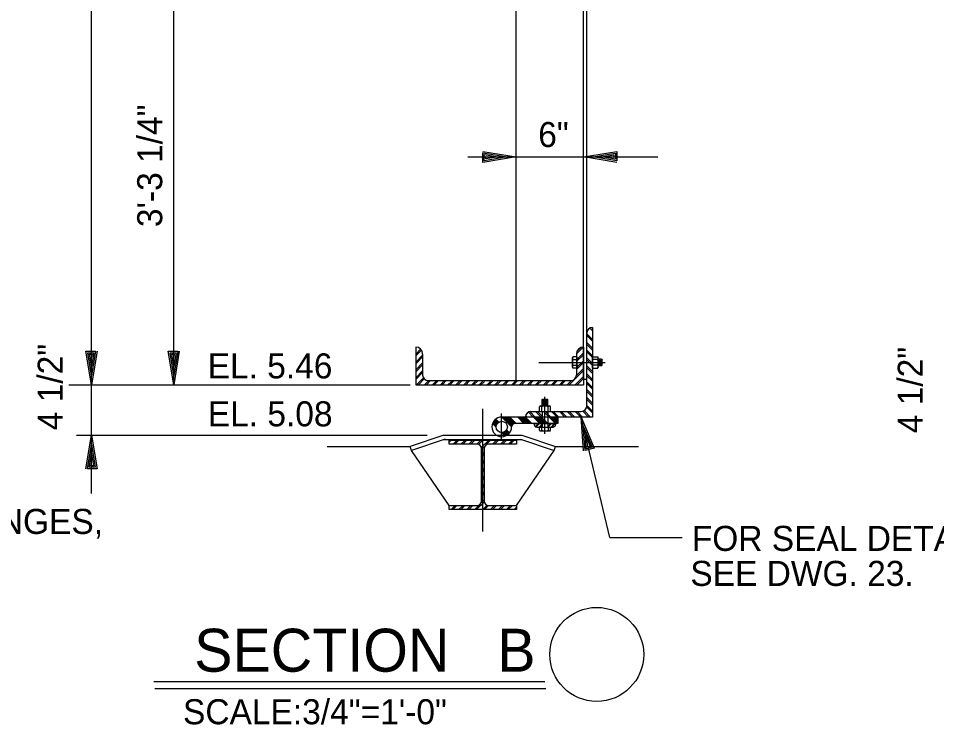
# Model space of a CAD drawing. Extents: x 0.6 to 54, y 0.6 to 38.
# Drawn here: x 40.38 to 47.23, y 11.68 to 16.93 of the extents above; entities that cross this region are included whole.
import ezdxf

# ---------------------------------------------------------------- set-up
doc = ezdxf.new("R2010")
doc.units = 0
for name, color, linetype in [('Level 1', 7, 'Continuous'), ('Level 10', 7, 'Continuous'), ('Level 13', 7, 'Continuous'), ('Level 2', 7, 'Continuous'), ('Level 25', 7, 'Continuous'), ('Level 3', 7, 'Continuous'), ('Level 36', 7, 'Continuous'), ('Level 50', 7, 'Continuous')]:
    doc.layers.add(name, color=color, linetype=linetype)

msp = doc.modelspace()

# ---------------------------------------------------------------- linework, layer by layer
at = {"layer": 'Level 1'}
msp.add_line((44.2486, 13.8913), (44.3689, 13.8913), dxfattribs=at)
for centre, start, end in [((44.251, 13.9174), 180, 270), ((44.3656, 13.9174), 270, 0)]:
    msp.add_arc(centre, 0.026, start, end, dxfattribs=at)
at = {"layer": 'Level 10'}
for p, q in [((44.2316, 13.9174), (44.2257, 13.9115)), ((44.2375, 13.9174), (44.2271, 13.907)), ((44.261, 13.9174), (44.2383, 13.8947)), ((44.2669, 13.9174), (44.2424, 13.8928)), ((44.2841, 13.9109), (44.2644, 13.8913)), ((44.2841, 13.9051), (44.2703, 13.8913)), ((44.3569, 13.9174), (44.3326, 13.8931)), ((44.351, 13.9174), (44.3326, 13.899)), ((44.3804, 13.9174), (44.3544, 13.8913)), ((44.3863, 13.9174), (44.3603, 13.8913))]:
    msp.add_line(p, q, dxfattribs=at)
at = {"layer": 'Level 13'}
for p, q in [((44.5137, 14.4087), (44.5169, 14.4143)), ((44.5137, 14.3362), (44.5137, 14.4087)), ((44.5168, 14.3934), (44.5476, 14.3934)), ((44.5476, 14.4143), (44.5169, 14.4143)), ((44.5476, 14.3306), (44.5476, 14.4143)), ((44.5491, 14.3967), (44.5476, 14.3967)), ((44.6613, 14.3967), (44.6628, 14.3967)), ((44.6628, 14.3306), (44.6628, 14.4143)), ((44.6628, 14.4143), (44.7026, 14.4143)), ((44.7027, 14.3934), (44.6628, 14.3934)), ((44.7058, 14.4087), (44.7026, 14.4143)), ((44.7058, 14.3362), (44.7058, 14.4087)), ((44.7293, 14.3967), (44.7058, 14.3967)), ((44.7111, 14.3544), (44.7111, 14.3904)), ((44.7171, 14.3482), (44.7171, 14.3967)), ((44.7232, 14.3544), (44.7232, 14.3904)), ((44.7293, 14.3482), (44.7293, 14.3967)), ((44.7293, 14.3967), (44.7353, 14.3907)), ((44.7353, 14.3543), (44.7353, 14.3907)), ((44.5137, 14.3362), (44.5169, 14.3306)), ((44.5168, 14.3515), (44.5476, 14.3515)), ((44.5476, 14.3306), (44.5169, 14.3306)), ((44.5476, 14.3518), (44.5476, 14.3306)), ((44.5491, 14.3482), (44.5476, 14.3482)), ((44.6613, 14.3482), (44.6628, 14.3482)), ((44.7027, 14.3515), (44.6628, 14.3515)), ((44.6628, 14.3306), (44.7026, 14.3306)), ((44.7058, 14.3362), (44.7026, 14.3306)), ((44.7293, 14.3482), (44.7058, 14.3482)), ((44.7293, 14.3482), (44.7353, 14.3543)), ((44.2878, 14.0974), (44.29, 14.0996)), ((44.2878, 14.0975), (44.3295, 14.0975)), ((44.29, 14.0996), (44.3274, 14.0996)), ((44.3295, 14.0973), (44.3274, 14.0996)), ((44.267, 14.0079), (44.267, 14.0412)), ((44.2755, 14.0495), (44.3419, 14.0495)), ((44.2842, 14.0079), (44.2842, 14.0412)), ((44.2878, 14.0495), (44.2878, 14.0974)), ((44.2878, 14.0891), (44.3295, 14.0891)), ((44.2878, 14.0809), (44.3295, 14.0809)), ((44.2878, 14.0725), (44.3295, 14.0725)), ((44.2878, 14.0641), (44.3295, 14.0641)), ((44.2878, 14.0559), (44.3295, 14.0559)), ((44.2983, 14.0934), (44.3201, 14.0934)), ((44.2983, 14.085), (44.3201, 14.085)), ((44.2983, 14.0766), (44.3201, 14.0766)), ((44.2983, 14.0684), (44.3201, 14.0684)), ((44.2983, 14.06), (44.3201, 14.06)), ((44.2983, 14.0516), (44.3201, 14.0516)), ((44.3295, 14.0495), (44.3295, 14.0973)), ((44.3335, 14.0079), (44.3335, 14.0412)), ((44.3503, 14.0079), (44.3503, 14.0412)), ((44.4034, 13.9654), (43.9867, 13.9654)), ((43.9874, 13.9654), (44.0596, 13.8932)), ((43.9911, 13.9654), (44.0599, 13.8966)), ((43.9948, 13.9654), (44.0606, 13.8996)), ((43.9984, 13.9654), (44.0616, 13.9023)), ((44.0021, 13.9654), (44.0627, 13.9049)), ((44.0058, 13.9654), (44.0639, 13.9074)), ((44.0095, 13.9654), (44.0657, 13.9093)), ((44.0132, 13.9654), (44.0676, 13.911)), ((44.0169, 13.9654), (44.0694, 13.9129)), ((44.0206, 13.9654), (44.0716, 13.9144)), ((44.0243, 13.9654), (44.0739, 13.9158)), ((44.0279, 13.9654), (44.0765, 13.9169)), ((44.0316, 13.9654), (44.0793, 13.9178)), ((44.0353, 13.9654), (44.0824, 13.9184)), ((44.039, 13.9654), (44.0859, 13.9186)), ((44.0426, 13.9654), (44.0895, 13.9186)), ((44.0463, 13.9654), (44.0932, 13.9186)), ((44.1053, 13.9654), (44.1521, 13.9186)), ((44.1089, 13.9654), (44.1558, 13.9186)), ((44.1126, 13.9654), (44.1595, 13.9186)), ((44.1163, 13.9654), (44.1632, 13.9186)), ((44.12, 13.9654), (44.1669, 13.9186)), ((44.12, 13.9654), (44.1632, 13.9223)), ((44.1237, 13.9654), (44.1706, 13.9186)), ((44.1274, 13.9654), (44.1742, 13.9186)), ((44.1311, 13.9654), (44.1779, 13.9186)), ((44.1347, 13.9654), (44.1816, 13.9186)), ((44.1384, 13.9654), (44.1853, 13.9186)), ((44.1421, 13.9654), (44.189, 13.9186)), ((44.1458, 13.9654), (44.1927, 13.9186)), ((44.1494, 13.9654), (44.1963, 13.9186)), ((44.1531, 13.9654), (44.2, 13.9186)), ((44.1568, 13.9654), (44.2037, 13.9186)), ((44.1605, 13.9654), (44.2074, 13.9186)), ((44.1642, 13.9654), (44.2111, 13.9186)), ((44.2231, 13.9654), (44.27, 13.9186)), ((44.2268, 13.9654), (44.2737, 13.9186)), ((44.2305, 13.9654), (44.2774, 13.9186)), ((44.2342, 13.9654), (44.2811, 13.9186)), ((44.2378, 13.9654), (44.2847, 13.9186)), ((44.2415, 13.9654), (44.2884, 13.9186)), ((44.2452, 13.9654), (44.2921, 13.9186)), ((44.2489, 13.9654), (44.2958, 13.9186)), ((44.2526, 13.9654), (44.2994, 13.9186)), ((44.2563, 13.9654), (44.3031, 13.9186)), ((44.2599, 13.9654), (44.3068, 13.9186)), ((44.2636, 13.9654), (44.3105, 13.9186)), ((44.2673, 13.9654), (44.3142, 13.9186)), ((44.271, 13.9654), (44.3179, 13.9186)), ((44.2747, 13.9654), (44.3216, 13.9186)), ((44.2784, 13.9654), (44.3252, 13.9186)), ((44.282, 13.9654), (44.3289, 13.9186)), ((44.2878, 14.0079), (44.2878, 13.8906)), ((44.3295, 14.0079), (44.3295, 13.8906)), ((44.3409, 13.9654), (44.3878, 13.9186)), ((44.3446, 13.9654), (44.3915, 13.9186)), ((44.3483, 13.9654), (44.3952, 13.9186)), ((44.352, 13.9654), (44.3989, 13.9186)), ((44.3557, 13.9654), (44.4026, 13.9186)), ((44.3594, 13.9654), (44.4034, 13.9214)), ((44.3631, 13.9654), (44.4034, 13.9251)), ((44.3667, 13.9654), (44.4034, 13.9288)), ((44.3704, 13.9654), (44.4034, 13.9325)), ((44.3741, 13.9654), (44.4034, 13.9361)), ((44.3778, 13.9654), (44.4034, 13.9398)), ((44.3814, 13.9654), (44.4034, 13.9435)), ((44.3851, 13.9654), (44.4034, 13.9472)), ((44.3888, 13.9654), (44.4034, 13.9509)), ((44.3925, 13.9654), (44.4034, 13.9546)), ((44.3962, 13.9654), (44.4034, 13.9583)), ((44.3999, 13.9654), (44.4034, 13.9619)), ((44.4034, 13.9654), (44.4034, 13.9186)), ((43.918, 13.917), (43.9451, 13.8899)), ((43.919, 13.9197), (43.9451, 13.8937)), ((43.9201, 13.9223), (43.9453, 13.8971)), ((43.9213, 13.9248), (43.9458, 13.9003)), ((43.9226, 13.9272), (43.9465, 13.9033)), ((43.9239, 13.9295), (43.9473, 13.9061)), ((43.9253, 13.9318), (43.9483, 13.9088)), ((43.9268, 13.934), (43.9495, 13.9113)), ((43.9283, 13.9362), (43.9508, 13.9137)), ((43.9299, 13.9383), (43.9519, 13.9162)), ((43.9316, 13.9403), (43.9538, 13.9181)), ((43.9333, 13.9422), (43.9554, 13.9201)), ((43.9351, 13.9441), (43.9572, 13.922)), ((43.9371, 13.9458), (43.9591, 13.9238)), ((43.939, 13.9476), (43.9612, 13.9254)), ((43.941, 13.9493), (43.9633, 13.927)), ((43.943, 13.9509), (43.9655, 13.9284)), ((44.4034, 13.9186), (44.0857, 13.9186)), ((43.9841, 13.8509), (44.0112, 13.8238)), ((43.9878, 13.8509), (44.0139, 13.8248)), ((43.9913, 13.8511), (44.0164, 13.8259)), ((43.9945, 13.8516), (44.0189, 13.8271)), ((43.9975, 13.8523), (44.0214, 13.8284)), ((44.0003, 13.8531), (44.0237, 13.8297)), ((44.003, 13.8542), (44.026, 13.8311)), ((44.0055, 13.8553), (44.0282, 13.8326)), ((44.0079, 13.8566), (44.0304, 13.8341)), ((44.0101, 13.8581), (44.0324, 13.8357)), ((44.0123, 13.8596), (44.0344, 13.8374)), ((44.0143, 13.8612), (44.0364, 13.8391)), ((44.0162, 13.8631), (44.0383, 13.8409)), ((44.0179, 13.8649), (44.04, 13.8429)), ((44.0196, 13.867), (44.0418, 13.8448)), ((44.0212, 13.8691), (44.0433, 13.847)), ((44.0226, 13.8713), (44.0451, 13.8488)), ((44.2676, 13.8913), (44.3509, 13.8913)), ((44.2676, 13.8678), (44.2676, 13.8913)), ((44.2761, 13.8622), (44.3426, 13.8622)), ((44.2848, 13.8676), (44.2848, 13.8913)), ((44.3341, 13.8677), (44.3341, 13.8913)), ((44.3509, 13.8678), (44.3509, 13.8913))]:
    msp.add_line(p, q, dxfattribs=at)
msp.add_circle((43.9867, 13.8925), 0.0417, dxfattribs=at)
for centre, radius, start, end in [((44.5318, 14.4037), 0.0182, 149.71241, 214.51098), ((44.5864, 14.3722), 0.0727, 163.01837, 196.49659), ((44.6877, 14.4038), 0.0182, 325.48902, 30.28759), ((44.6331, 14.3722), 0.0727, 343.50341, 16.98163), ((44.5318, 14.3412), 0.0182, 145.48902, 210.28759), ((44.6877, 14.3412), 0.0182, 329.71241, 34.51098), ((44.2754, 14.041), 0.00844, 0.56585, 179.43412), ((44.3088, 14.009), 0.0406, 52.43432, 127.56565), ((44.3419, 14.0411), 0.00843, 0.4975, 179.50247), ((43.9867, 13.8925), 0.0729, 90, 0), ((44.0857, 13.8925), 0.026, 90, 180), ((44.2762, 13.8715), 0.00938, 203.16754, 335.99909), ((44.3093, 13.9191), 0.0569, 244.55188, 295.884), ((44.3425, 13.8714), 0.00912, 202.37505, 337.19948)]:
    msp.add_arc(centre, radius, start, end, dxfattribs=at)
at = {"layer": 'Level 2'}
for p, q in [((44.225, 13.9174), (44.3916, 13.9174)), ((44.2841, 13.8913), (44.2841, 13.9174)), ((44.3326, 13.8913), (44.3326, 13.9174))]:
    msp.add_line(p, q, dxfattribs=at)
at = {"layer": 'Level 25'}
for p, q in [((40.9293, 14.206), (40.9293, 20.7475)), ((44.0951, 14.2373), (44.0951, 20.7162)), ((44.5951, 15.9049), (44.5951, 19.2475)), ((44.6212, 14.2477), (44.6212, 19.2475)), ((41.5423, 14.206), (41.5423, 17.4766)), ((43.7339, 15.9029), (44.0951, 15.9029)), ((44.0951, 15.9029), (44.5951, 15.9029)), ((44.5951, 14.2535), (44.5951, 15.9049)), ((44.5951, 15.9029), (45.151, 15.9029)), ((44.6628, 14.5441), (44.6212, 14.5857)), ((44.6628, 14.6086), (44.6433, 14.6281)), ((44.6628, 14.6246), (44.6552, 14.6322)), ((44.6628, 14.5304), (44.6212, 14.572)), ((44.6628, 14.4797), (44.6212, 14.5214)), ((43.3451, 14.4873), (43.3451, 14.206)), ((43.3823, 14.4717), (43.3451, 14.4346)), ((43.3885, 14.464), (43.3451, 14.4207)), ((44.5951, 14.4892), (44.5434, 14.4374)), ((44.5951, 14.4441), (44.546, 14.3951)), ((44.5755, 14.4834), (44.5489, 14.4568)), ((44.5951, 14.4873), (44.5951, 14.206)), ((44.6628, 14.4649), (44.6212, 14.5065)), ((44.6628, 14.4229), (44.6212, 14.4646)), ((44.6628, 14.409), (44.6212, 14.4507)), ((43.3972, 14.4277), (43.3451, 14.3756)), ((43.3972, 14.4138), (43.3451, 14.3617)), ((43.3972, 14.4352), (43.3972, 14.2789)), ((44.2621, 14.3725), (44.7583, 14.3725)), ((44.5951, 14.3713), (44.5429, 14.3191)), ((44.543, 14.4352), (44.543, 14.2789)), ((44.5951, 14.4303), (44.5436, 14.3787)), ((44.5951, 14.3852), (44.5438, 14.3339)), ((44.6628, 14.364), (44.6212, 14.4057)), ((44.6628, 14.3501), (44.6212, 14.3918)), ((43.3972, 14.3688), (43.3451, 14.3167)), ((43.3972, 14.3549), (43.3451, 14.3028)), ((43.3972, 14.3099), (43.3451, 14.2578)), ((44.5951, 14.3124), (44.4887, 14.206)), ((44.5951, 14.3263), (44.5449, 14.2761)), ((44.6628, 14.3051), (44.6212, 14.3467)), ((44.6628, 14.2912), (44.6212, 14.3329)), ((43.3972, 14.2965), (43.3451, 14.2445)), ((43.4033, 14.2572), (43.3522, 14.206)), ((43.4094, 14.2494), (43.366, 14.206)), ((43.4415, 14.2364), (43.4111, 14.206)), ((43.4563, 14.2373), (43.425, 14.206)), ((43.5, 14.236), (43.4701, 14.206)), ((43.5159, 14.238), (43.4839, 14.206)), ((43.5606, 14.2377), (43.529, 14.206)), ((43.576, 14.2398), (43.5458, 14.2095)), ((43.7471, 14.2345), (43.7152, 14.2025)), ((43.8073, 14.2363), (43.777, 14.206)), ((44.0368, 14.2345), (44.0065, 14.2043)), ((44.2218, 14.2345), (44.1899, 14.2025)), ((44.2819, 14.2363), (44.2517, 14.206)), ((44.3283, 14.2362), (44.2981, 14.206)), ((44.3422, 14.2363), (44.3119, 14.206)), ((44.3874, 14.2364), (44.357, 14.206)), ((44.4022, 14.2373), (44.3709, 14.206)), ((44.4459, 14.2359), (44.4159, 14.206)), ((44.4618, 14.238), (44.4298, 14.206)), ((44.5065, 14.2377), (44.4748, 14.206)), ((44.5951, 14.2674), (44.5338, 14.206)), ((44.5951, 14.2535), (44.5477, 14.206)), ((44.5951, 14.2477), (44.6212, 14.2477)), ((44.6628, 14.2461), (44.6212, 14.2878)), ((44.6628, 14.2323), (44.6212, 14.2739)), ((40.7614, 14.206), (43.3044, 14.206)), ((40.9293, 13.8308), (40.9293, 14.206)), ((43.6136, 14.2327), (43.5834, 14.2025)), ((43.6275, 14.2328), (43.5973, 14.2025)), ((43.6727, 14.2329), (43.6423, 14.2025)), ((43.6875, 14.2338), (43.6562, 14.2025)), ((43.7312, 14.2325), (43.7013, 14.2025)), ((43.7919, 14.2342), (43.7602, 14.2025)), ((43.8431, 14.231), (43.8129, 14.2008)), ((43.857, 14.231), (43.8267, 14.2008)), ((43.9022, 14.2312), (43.8718, 14.2008)), ((43.917, 14.2321), (43.8857, 14.2008)), ((43.9607, 14.2307), (43.9308, 14.2008)), ((43.9766, 14.2327), (43.9447, 14.2008)), ((44.0214, 14.2324), (43.9897, 14.2008)), ((44.0883, 14.2327), (44.0581, 14.2025)), ((44.1022, 14.2328), (44.0719, 14.2025)), ((44.1474, 14.2329), (44.117, 14.2025)), ((44.1622, 14.2338), (44.1309, 14.2025)), ((44.2059, 14.2325), (44.176, 14.2025)), ((44.2666, 14.2342), (44.2349, 14.2025)), ((44.5951, 14.2084), (44.5927, 14.206)), ((44.6628, 14.1872), (44.6212, 14.2289)), ((44.6628, 14.1733), (44.6212, 14.215)), ((44.6628, 14.1283), (44.6212, 14.17)), ((44.3087, 13.8401), (44.3087, 14.1157)), ((44.6628, 14.1144), (44.6212, 14.1561)), ((44.6628, 14.0694), (44.6212, 14.111)), ((44.6628, 13.9966), (44.6196, 14.0398)), ((44.6628, 14.0555), (44.6212, 14.0971)), ((44.6628, 14.0104), (44.6212, 14.0521)), ((43.8455, 13.1143), (43.8455, 14.0271)), ((43.9857, 13.7906), (43.9857, 13.9926)), ((44.1767, 13.9662), (44.1647, 13.9783)), ((44.2218, 13.9662), (44.1851, 14.0028)), ((44.2356, 13.9662), (44.1953, 14.0066)), ((44.2807, 13.9662), (44.239, 14.0079)), ((44.2946, 13.9662), (44.2529, 14.0079)), ((44.3396, 13.9662), (44.2979, 14.0079)), ((44.3535, 13.9662), (44.3118, 14.0079)), ((44.3985, 13.9662), (44.3569, 14.0079)), ((44.4124, 13.9662), (44.3708, 14.0079)), ((44.4574, 13.9662), (44.4158, 14.0079)), ((44.4713, 13.9662), (44.4297, 14.0079)), ((44.5164, 13.9662), (44.4747, 14.0079)), ((44.5303, 13.9662), (44.4886, 14.0079)), ((44.5753, 13.9662), (44.5336, 14.0079)), ((44.5892, 13.9662), (44.5475, 14.0079)), ((44.7926, 13.0686), (44.5779, 13.9662)), ((44.6342, 13.9662), (44.5909, 14.0095)), ((44.6481, 13.9662), (44.6005, 14.0138)), ((40.8162, 13.8308), (43.4301, 13.8308)), ((40.9293, 13.3969), (40.9293, 13.8308)), ((43.5539, 13.8308), (43.3039, 13.7475)), ((43.5539, 13.8308), (44.1372, 13.8308)), ((44.1372, 13.8308), (44.3872, 13.7475)), ((43.5637, 13.8012), (43.3137, 13.7178)), ((43.5539, 13.7996), (44.1372, 13.7996)), ((43.595, 13.7939), (43.595, 13.7939)), ((43.595, 13.78), (43.6089, 13.7939)), ((43.6235, 13.7635), (43.6539, 13.7939)), ((43.6374, 13.7635), (43.6678, 13.7939)), ((43.6825, 13.7635), (43.7129, 13.7939)), ((43.6963, 13.7635), (43.7268, 13.7939)), ((43.7414, 13.7635), (43.7718, 13.7939)), ((43.7553, 13.7635), (43.7857, 13.7939)), ((43.8003, 13.7635), (43.8307, 13.7939)), ((43.8126, 13.7619), (43.8446, 13.7939)), ((43.8339, 13.7382), (43.8896, 13.7939)), ((43.835, 13.7254), (43.9035, 13.7939)), ((43.9182, 13.7635), (43.9486, 13.7939)), ((43.932, 13.7635), (43.9625, 13.7939)), ((43.9771, 13.7635), (44.0075, 13.7939)), ((43.991, 13.7635), (44.0214, 13.7939)), ((44.036, 13.7635), (44.0664, 13.7939)), ((44.0499, 13.7635), (44.0803, 13.7939)), ((44.0949, 13.7635), (44.0967, 13.7653)), ((44.1273, 13.8012), (44.3773, 13.7178)), ((42.685, 13.7475), (43.3039, 13.7475)), ((43.3138, 13.7178), (43.3039, 13.7475)), ((43.595, 13.3077), (43.3137, 13.7178)), ((43.835, 13.6804), (43.8567, 13.702)), ((43.835, 13.6665), (43.8567, 13.6882)), ((44.0967, 13.3077), (44.3773, 13.7178)), ((44.3773, 13.7178), (44.3872, 13.7475)), ((44.3872, 13.7475), (45.0067, 13.7475)), ((43.835, 13.6214), (43.8567, 13.6431)), ((43.835, 13.6076), (43.8567, 13.6292)), ((43.835, 13.5625), (43.8567, 13.5842)), ((43.835, 13.5486), (43.8567, 13.5703)), ((43.835, 13.5036), (43.8567, 13.5253)), ((43.835, 13.4897), (43.8567, 13.5114)), ((43.835, 13.4447), (43.8567, 13.4663)), ((43.835, 13.4308), (43.8567, 13.4524)), ((43.7855, 13.2773), (43.8567, 13.3485)), ((43.835, 13.3858), (43.8567, 13.4074)), ((43.835, 13.3719), (43.8567, 13.3935)), ((43.6087, 13.2773), (43.6391, 13.3077)), ((43.6226, 13.2773), (43.653, 13.3077)), ((43.6676, 13.2773), (43.698, 13.3077)), ((43.6815, 13.2773), (43.7119, 13.3077)), ((43.7265, 13.2773), (43.7569, 13.3077)), ((43.7404, 13.2773), (43.7708, 13.3077)), ((43.7994, 13.2773), (43.8574, 13.3353)), ((43.8444, 13.2773), (43.8773, 13.3102)), ((43.8583, 13.2773), (43.8887, 13.3077)), ((43.9033, 13.2773), (43.9337, 13.3077)), ((43.9172, 13.2773), (43.9476, 13.3077)), ((43.9622, 13.2773), (43.9927, 13.3077)), ((43.9761, 13.2773), (44.0065, 13.3077)), ((44.0212, 13.2773), (44.0516, 13.3077)), ((44.0351, 13.2773), (44.0655, 13.3077)), ((44.0801, 13.2773), (44.0967, 13.2939)), ((44.094, 13.2773), (44.0967, 13.28)), ((44.7926, 13.0686), (45.33, 13.0686)), ((41.3937, 11.9959), (44.3069, 11.9959)), ((41.4012, 11.9452), (44.3144, 11.9452))]:
    msp.add_line(p, q, dxfattribs=at)
at = {"layer": 'Level 3'}
msp.add_circle((44.6944, 12.1984), 0.35, dxfattribs=at)
at = {"layer": 'Level 36'}
for p, q in [((44.6212, 14.0496), (44.6212, 14.5915)), ((44.6628, 14.6329), (44.6628, 13.9662)), ((44.6628, 13.9662), (44.1628, 13.9662)), ((44.2045, 14.0079), (44.5795, 14.0079)), ((43.595, 13.7939), (44.0967, 13.7939)), ((43.595, 13.7635), (43.595, 13.7939)), ((43.8029, 13.7635), (43.595, 13.7635)), ((44.0967, 13.7635), (43.8888, 13.7635)), ((44.0967, 13.7939), (44.0967, 13.7635)), ((43.835, 13.3398), (43.835, 13.7314)), ((43.8567, 13.7314), (43.8567, 13.3398)), ((43.595, 13.2773), (43.595, 13.3077)), ((43.595, 13.3077), (43.8029, 13.3077)), ((44.0967, 13.2773), (43.595, 13.2773)), ((43.8888, 13.3077), (44.0967, 13.3077)), ((44.0967, 13.3077), (44.0967, 13.2773))]:
    msp.add_line(p, q, dxfattribs=at)
for centre, radius, start, end in [((44.6628, 14.5912), 0.0417, 90, 180), ((44.5795, 14.0496), 0.0417, 270, 0), ((44.2045, 13.9662), 0.0417, 90, 180), ((43.8029, 13.7314), 0.0321, 0, 90), ((43.8888, 13.7314), 0.0321, 90, 180), ((43.8029, 13.3398), 0.0321, 270, 0), ((43.8888, 13.3398), 0.0321, 180, 270)]:
    msp.add_arc(centre, radius, start, end, dxfattribs=at)
at = {"layer": 'Level 50'}
for p, q in [((44.0258, 15.9029), (44.0258, 15.9029)), ((44.0951, 15.9029), (44.0951, 15.9029)), ((44.5951, 15.9029), (44.5951, 15.9029)), ((44.6644, 15.9029), (44.6644, 15.9029)), ((40.9293, 14.2753), (40.9293, 14.2753)), ((41.5423, 14.2753), (41.5423, 14.2753)), ((43.4389, 14.2373), (44.5014, 14.2373)), ((40.9293, 14.206), (40.9293, 14.206)), ((41.5423, 14.206), (41.5423, 14.206)), ((43.3451, 14.206), (44.5951, 14.206)), ((44.5779, 13.9662), (44.5779, 13.9662)), ((44.5941, 13.8988), (44.5941, 13.8988)), ((40.9293, 13.8308), (40.9293, 13.8308)), ((40.9293, 13.7615), (40.9293, 13.7615))]:
    msp.add_line(p, q, dxfattribs=at)
for points in [[(43.8458, 15.9443), (44.0951, 15.9029), (43.8458, 15.8616), (43.8458, 15.9323), (44.0258, 15.9029), (43.8564, 15.8749), (43.8564, 15.9203), (43.9591, 15.9029), (43.8671, 15.8883), (43.8671, 15.9069), (43.8898, 15.9029)], [(44.8444, 15.8616), (44.5951, 15.9029), (44.8444, 15.9443), (44.8444, 15.8736), (44.6644, 15.9029), (44.8338, 15.9309), (44.8338, 15.8856), (44.7311, 15.9029), (44.8231, 15.9176), (44.8231, 15.8989), (44.8004, 15.9029)], [(40.9706, 14.4553), (40.9293, 14.206), (40.8879, 14.4553), (40.9586, 14.4553), (40.9293, 14.2753), (40.9013, 14.4447), (40.9466, 14.4447), (40.9293, 14.342), (40.9146, 14.434), (40.9333, 14.434), (40.9293, 14.4113)], [(41.5836, 14.4553), (41.5423, 14.206), (41.5009, 14.4553), (41.5716, 14.4553), (41.5423, 14.2753), (41.5143, 14.4447), (41.5596, 14.4447), (41.5423, 14.342), (41.5276, 14.434), (41.5463, 14.434), (41.5423, 14.4113)], [(44.5957, 13.7141), (44.5779, 13.9662), (44.6761, 13.7333), (44.6074, 13.7169), (44.5941, 13.8988), (44.6607, 13.7406), (44.6166, 13.7301), (44.6096, 13.8339), (44.6452, 13.7479), (44.6271, 13.7435), (44.6257, 13.7665)], [(40.8879, 13.5815), (40.9293, 13.8308), (40.9706, 13.5815), (40.8999, 13.5815), (40.9293, 13.7615), (40.9573, 13.5921), (40.9119, 13.5921), (40.9293, 13.6948), (40.9439, 13.6028), (40.9253, 13.6028), (40.9293, 13.6255)]]:
    msp.add_lwpolyline(points, dxfattribs=at)
for centre, radius, start, end in [((43.3451, 14.4352), 0.0521, 0, 90), ((44.5951, 14.4352), 0.0521, 90, 180), ((43.4389, 14.2789), 0.0417, 180, 270), ((44.5014, 14.2789), 0.0417, 270, 0)]:
    msp.add_arc(centre, radius, start, end, dxfattribs=at)

# ---------------------------------------------------------------- texts
at = {"layer": 'Level 2'}
msp.add_text('SECTION   B', height=0.32, dxfattribs=at).set_placement((41.6944, 12.0696))
at = {"layer": 'Level 25'}
for s, p in [('3\'-3 1/4"', (41.4563, 15.3803)), ('4 1/2"', (40.7147, 13.8675)), ('4 1/2"', (47.1243, 13.8452))]:
    msp.add_text(s, height=0.18667, rotation=90, dxfattribs=at).set_placement(p)
for s, height, p in [('6"', 0.18667, (44.2583, 15.9763)), ('EL. 5.46', 0.18667, (41.7947, 14.2536)), ('EL. 5.08', 0.18667, (41.7958, 13.8965)), ('HOLES 1 1/16" 0 FOR HINGES,', 0.186667, (37.4169, 13.0953)), ('FOR SEAL DETAIL', 0.186667, (45.4028, 12.9691)), ('SEE DWG. 23.', 0.186667, (45.3922, 12.7084)), ('SCALE:3/4"=1\'-0"', 0.186667, (41.6113, 11.6782))]:
    msp.add_text(s, height=height, dxfattribs=at).set_placement(p)

doc.saveas('drawing.dxf')
